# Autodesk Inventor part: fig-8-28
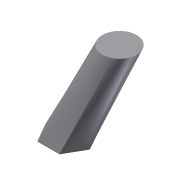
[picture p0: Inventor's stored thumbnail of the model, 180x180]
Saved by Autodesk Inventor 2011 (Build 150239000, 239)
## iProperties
Shininess: 77.0
Angle Display Precision: 2
Document Length Units: 11269
Document Angle Units: 11279
Document Time Units: 11290
Document Mass Units: 11283
Document Length Units Precision: 3
Document Angle Units Precision: 2
Created: 2001-12
Part Number: fig-8-28
Document SubType Name: Modeling
Designer: CADSoft
Density: 1 g/cm^3
Density: 0.0
Volumn: 0.0
Area: 0.0
PropertySet Name: Model Information
Control State: 0
Master: False
Checked Out: False
Author: CADSoft
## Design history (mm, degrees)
workplane "Work Plane3"
workplane "Work Plane4"
sketch "Sketch12"
  geometry: L1 (0, 10.598)-(9.178, -5.299); L2 (9.178, -5.299)-(-9.178, -5.299); L3 (-9.178, -5.299)-(0, 10.598); 1 further point
  constraints: 6 end point, 5 other
workplane "Work Plane5"
workplane "Work Plane6"
workplane "Work Plane7"
sketch "Sketch16"
  geometry: A1 r 72.799 centre (23.007, 110.594) between (0, 41.527) and (70, 54.995); 1 further point
  constraints: 2 point on circle, 1 centre point
loft "Loft5" dims "d57" = 0, "d58" = 90 deg, "d59" = 0, "d60" = 90 deg
body "Solid2"
sketch "Sketch1"
  geometry: L1 (19.387, 0)-(9.693, -16.79); L2 (9.693, -16.79)-(-9.693, -16.79); L3 (-9.693, -16.79)-(-19.387, 0); L4 (-19.387, 0)-(-9.693, 16.79); L5 (-9.693, 16.79)-(9.693, 16.79); L6 (9.693, 16.79)-(19.387, 0); 1 further point
  constraints: 12 end point, 11 other
sketch "Sketch2"
  geometry: C1 r 15 at (23.06, 22.535)
  constraints: 1 centre point
